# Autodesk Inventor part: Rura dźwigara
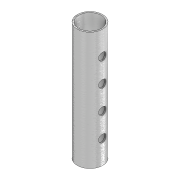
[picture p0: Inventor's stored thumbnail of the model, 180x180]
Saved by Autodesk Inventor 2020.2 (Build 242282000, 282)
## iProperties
Created: 2011-11
Part Number: Rura dźwigara
Material: Stal
Document SubType Name: Modeling
Designer: F.Stasiak
Density: 7.85 g/cm^3
Mass: 904.994 g
Surface Area: 791.157 cm^2
Volume: 115.286 cm^3
Appearance: Stal
Catalog Web Link: www.expertbooks.pl
Manager: www.cadconsulting.pl
Company: Fabian Stasiak CAD Consulting
Author: F.Stasiak
Subject: Zbiór ćwiczeń. Autodesk Inventor 2020. Kurs Professional
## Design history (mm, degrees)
sketch "Szkic1"
  geometry: C1 r 27 at (0, 0); C2 r 24 at (0, 0); 1 further point
  constraints: 2 centre point, 2 coincident
  dimensions: "d0" = 54 diameter of C1; "GRUBOŚĆ_RURY_DŹWIGARA" = 3 radial gap between concentric circles of C2 C1
extrude "Wyciągnięcie proste1" new body sketch "Szkic1" distance "d2" = 250; taper "d3" = 0 deg
sketch "Szkic2"
  geometry: L1 (-24, 0)-(24, 0) reference; C1 r 8 at (0, -50); 2 further points
  constraints: 1 centre point, 1 midpoint, 1 vertical alignment
  dimensions: "d4" = 16 diameter of C1; "d5" = 50 distance from line of L1 C1.centre
extrude "Wyciągnięcie proste2" cut sketch "Szkic2" extent not by distance; stored distance "d6" = 250; taper "d7" = 0 deg
pattern_linear "Szyk prostokątny1" dims "d10" = 50
node "Bryła1"
